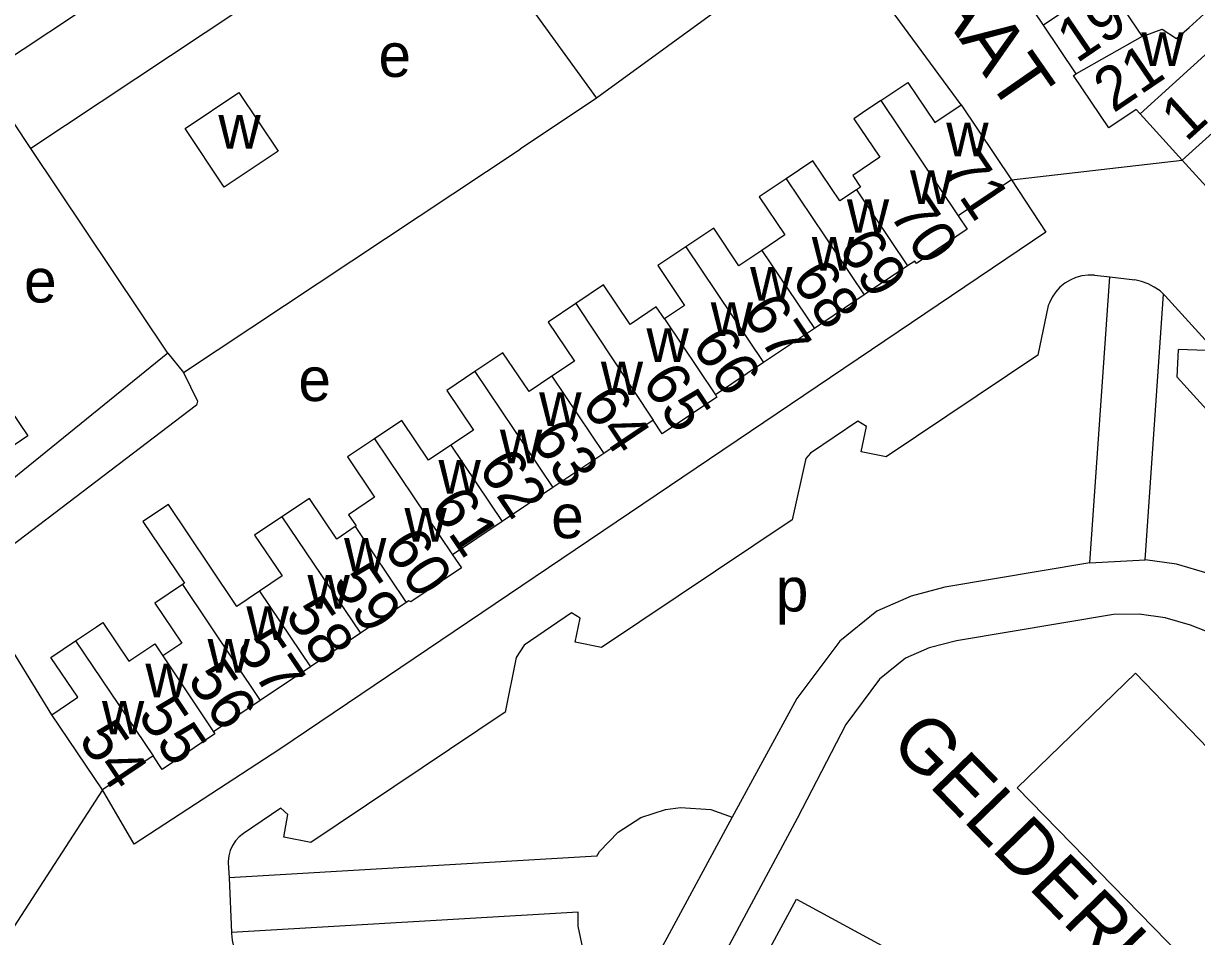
# Model space of a CAD drawing. Extents: x 158356 to 159894, y 383831 to 385260.
# Drawn here: x 158893.5 to 159000.7, y 384127.4 to 384210.9 of the extents above; entities that cross this region are included whole.
import ezdxf

# ---------------------------------------------------------------- set-up
doc = ezdxf.new("R2010")
doc.units = 0
for name, color, linetype in [('BLT_Basislijn', 7, 'Continuous'), ('BLT_Bebouwing', 7, 'Continuous'), ('BLT_Centroide', 7, 'Continuous'), ('BLT_Huisnummer', 7, 'Continuous'), ('BLT_Huisnummer_ tussenligend', 7, 'Continuous'), ('BLT_Onderverdeling_panden', 7, 'Continuous'), ('BLT_Straatnaam', 7, 'Continuous'), ('BLT_Vlakafsluiter', 7, 'Continuous')]:
    doc.layers.add(name, color=color, linetype=linetype)

msp = doc.modelspace()

# ---------------------------------------------------------------- linework, layer by layer
at = {"layer": 'BLT_Basislijn'}
for p, q in [((158930.73, 384224.98), (158945.89, 384204.06)), ((158979.18, 384203.45), (158967.44, 384219.43)), ((158961.44, 384215.4), (158945.89, 384204.06)), ((158945.89, 384204.06), (158938.9, 384199.39)), ((158906.7, 384180.74), (158894.19, 384199.45)), ((158908.13, 384178.98), (158938.9, 384199.39)), ((158990.95, 384161.58), (158992.79, 384187.71)), ((158991.37, 384187.88), (158992.79, 384187.71)), ((158992.79, 384187.71), (158995.07, 384187.44)), ((158995.99, 384161.86), (158997.69, 384186.13)), ((158987.13, 384185.1), (158986.2, 384180.57)), ((158906.7, 384180.74), (158891.84, 384168.68)), ((158906.7, 384180.74), (158908.13, 384178.98)), ((158986.2, 384180.57), (158972.33, 384171.27)), ((158990.95, 384161.58), (158995.99, 384161.86)), ((158896.12, 384147.7), (158888.48, 384160.12)), ((158964.18, 384149.17), (158958.27, 384138.32)), ((158958.27, 384138.32), (158948.85, 384120.94)), ((158912.23, 384134.16), (158912.3, 384132.79)), ((158945.92, 384134.77), (158912.3, 384132.79)), ((158912.3, 384132.79), (158912.53, 384127.8)), ((158944.2, 384129.66), (158912.53, 384127.8)), ((158912.53, 384127.8), (158912.54, 384127.69))]:
    msp.add_line(p, q, dxfattribs=at)
for points in [[(158983.8, 384196.58), (158986.94, 384191.81), (158916.93, 384144.54), (158903.63, 384135.86), (158900.74, 384140.84)], [(158991.37, 384187.88), (158990.8, 384187.89), (158990.23, 384187.81), (158989.68, 384187.66), (158989.15, 384187.43), (158988.66, 384187.13), (158988.22, 384186.77), (158987.83, 384186.35), (158987.51, 384185.88), (158987.25, 384185.36), (158987.13, 384185.1)], [(158997.69, 384186.13), (158997.36, 384186.43), (158996.83, 384186.79), (158996.27, 384187.08), (158995.68, 384187.3), (158995.07, 384187.44)], [(158997.83, 384186), (158997.69, 384186.13)], [(158997.83, 384186), (159001.78, 384181.62), (159001.54, 384181), (158999.06, 384181.08)], [(159010.91, 384165.35), (158998.93, 384178.56), (158999.06, 384181.08)], [(158908.13, 384178.98), (158909.41, 384176.35), (158909.32, 384175.99), (158888.48, 384160.12)], [(158972.33, 384171.27), (158970.07, 384171.72), (158970.54, 384174.05), (158969.76, 384174.53), (158965.43, 384171.61), (158964.99, 384171.11), (158963.74, 384165.51), (158946.33, 384153.83), (158943.94, 384154.33), (158944.39, 384156.51), (158943.59, 384157), (158939.27, 384154.07), (158938.53, 384152.92), (158937.53, 384147.93)], [(159008.97, 384156.46), (159007.32, 384157.89), (159004.61, 384159.5), (159001.77, 384160.62), (158998.86, 384161.47), (158995.99, 384161.86)], [(158990.95, 384161.58), (158977.71, 384159.35), (158974.62, 384158.54), (158971.49, 384157.17), (158968.11, 384154.43), (158964.18, 384149.17)], [(159006.64, 384151.86), (159004.38, 384153.82), (159002.4, 384155), (159000.15, 384155.88), (158997.82, 384156.56), (158995.47, 384156.88), (158993.12, 384156.87), (158978.76, 384154.46), (158976.27, 384153.81), (158974.11, 384152.86), (158971.74, 384150.94), (158968.65, 384146.8)], [(158937.53, 384147.93), (158919.78, 384136.01), (158917.31, 384136.49), (158917.67, 384138.59), (158917.02, 384139.17), (158913.62, 384136.85)], [(158968.65, 384146.8), (158964.22, 384138.2), (158955.79, 384122.55)], [(158945.92, 384134.77), (158946.16, 384135.19), (158947.84, 384136.96), (158949.94, 384138.29), (158952.17, 384139.04), (158953.56, 384139.23), (158956.33, 384139.03), (158958.27, 384138.32)], [(158913.62, 384136.85), (158913.23, 384136.53), (158912.89, 384136.16), (158912.62, 384135.74), (158912.41, 384135.28), (158912.28, 384134.79), (158912.23, 384134.29), (158912.23, 384134.16)], [(158948.85, 384120.94), (158947.78, 384121.67), (158946.44, 384123.01), (158945.35, 384124.64), (158944.62, 384126.37), (158944.21, 384128.36), (158944.2, 384129.66)], [(158912.54, 384127.69), (158912.58, 384127.1), (158912.7, 384126.52), (158912.89, 384125.96), (158913.16, 384125.44), (158913.5, 384124.95), (158913.9, 384124.52), (158914.05, 384124.38)]]:
    msp.add_lwpolyline(points, dxfattribs=at)
for points in [[(158995.11, 384151.5), (159012.51, 384133.45), (159001.73, 384123.15), (158984.32, 384141.02)], [(158964.16, 384130.84), (158973.01, 384126.02), (158969.38, 384119.33), (158960.56, 384124.2)]]:
    msp.add_lwpolyline(points, close=True, dxfattribs=at)
at = {"layer": 'BLT_Bebouwing'}
for p, q in [((158889.79, 384206.08), (158915.33, 384223.05)), ((158986.7, 384210.73), (158983.81, 384215.04)), ((158989.69, 384206.28), (158986.7, 384210.73)), ((158894.19, 384199.45), (158889.79, 384206.08)), ((158908.28, 384201.27), (158913.2, 384204.58)), ((158913.2, 384204.58), (158916.79, 384199.22)), ((158979.18, 384203.45), (158983.8, 384196.58)), ((158999.39, 384198.39), (158995.54, 384202.63)), ((158911.87, 384195.92), (158908.28, 384201.27)), ((158916.79, 384199.22), (158911.87, 384195.92)), ((158983.8, 384196.58), (158978.92, 384193.3)), ((158974.28, 384188.72), (158970.34, 384186.07)), ((158970.34, 384186.07), (158965.78, 384183.01)), ((158965.78, 384183.01), (158961.13, 384179.89)), ((158961.13, 384179.89), (158956.75, 384176.94)), ((158951.05, 384174.62), (158946.53, 384171.58)), ((158946.53, 384171.58), (158941.89, 384168.46)), ((158941.89, 384168.46), (158937.27, 384165.36)), ((158937.27, 384165.36), (158932.73, 384162.31)), ((158928.49, 384157.95), (158924.3, 384155.14)), ((158924.3, 384155.14), (158919.74, 384152.07)), ((158919.74, 384152.07), (158915.16, 384148.99)), ((158915.16, 384148.99), (158910.89, 384146.13)), ((158900.74, 384140.84), (158896.12, 384147.7)), ((158905.36, 384143.94), (158900.74, 384140.84))]:
    msp.add_line(p, q, dxfattribs=at)
for points in [[(158915.33, 384223.05), (158919.73, 384216.42), (158894.19, 384199.45)], [(158996.17, 384217.09), (158997.79, 384214.66), (158994.06, 384212.16), (158995.72, 384209.68)], [(158995.72, 384209.68), (158997.57, 384210.35), (158998.88, 384209.5), (159000.03, 384210.53), (159002.36, 384212.65), (159004.27, 384210.55)], [(158995.54, 384202.63), (158995.17, 384203.03), (158992.67, 384201.35), (158989.46, 384206.13), (158989.69, 384206.28)], [(158971.85, 384203.83), (158974.32, 384205.48), (158976.78, 384201.83), (158979.18, 384203.45)], [(158971.85, 384203.83), (158970.17, 384202.7), (158969.39, 384202.17), (158971.75, 384198.65), (158969.28, 384196.99), (158970, 384195.92), (158969.62, 384195.67)], [(158969.62, 384195.67), (158968.12, 384194.66), (158965.65, 384198.33), (158963.2, 384196.68)], [(159003.21, 384194.18), (159000, 384197.72), (158999.39, 384198.39)], [(158963.2, 384196.68), (158960.75, 384195.04), (158963.09, 384191.55), (158960.99, 384190.14)], [(158978.92, 384193.3), (158979.75, 384192.07), (158975.11, 384188.94), (158974.95, 384189.17), (158974.28, 384188.72)], [(158960.99, 384190.14), (158958.89, 384188.73), (158956.58, 384192.17), (158954.03, 384190.46)], [(158954.03, 384190.46), (158951.48, 384188.75), (158953.92, 384185.11), (158952.09, 384183.88)], [(158952.09, 384183.88), (158951.34, 384184.98), (158948.94, 384183.37), (158946.52, 384186.98), (158944, 384185.28)], [(158944, 384185.28), (158941.47, 384183.58), (158943.86, 384180.03), (158941.79, 384178.64)], [(158941.79, 384178.64), (158939.71, 384177.24), (158937.33, 384180.78), (158934.77, 384179.06)], [(158934.77, 384179.06), (158932.2, 384177.33), (158934.63, 384173.72), (158932.58, 384172.34)], [(158956.75, 384176.94), (158956.87, 384176.73), (158951.88, 384173.38), (158951.05, 384174.62)], [(158892.35, 384175.53), (158893.93, 384173.18), (158890.41, 384170.81), (158891.84, 384168.68)], [(158932.58, 384172.34), (158930.52, 384170.96), (158928.08, 384174.59), (158925.6, 384172.92)], [(158925.6, 384172.92), (158923.12, 384171.26), (158925.6, 384167.57), (158923.23, 384165.98), (158923.92, 384164.95), (158923.83, 384164.89)], [(158923.83, 384164.89), (158922.14, 384163.75), (158919.64, 384167.47), (158917.14, 384165.79)], [(158915.09, 384158.99), (158913.02, 384157.6), (158910.55, 384161.27), (158906.78, 384166.9), (158904.43, 384165.36), (158908.23, 384159.71), (158908.04, 384159.59)], [(158917.14, 384165.79), (158914.64, 384164.11), (158917.15, 384160.38), (158915.09, 384158.99)], [(158932.73, 384162.31), (158933.54, 384161.11), (158928.92, 384158.01), (158928.72, 384158.11), (158928.49, 384157.95)], [(158908.04, 384159.59), (158905.53, 384157.9), (158907.98, 384154.25), (158906.24, 384153.08)], [(158898.29, 384154.46), (158900.18, 384155.73), (158900.78, 384156.13), (158903.15, 384152.59), (158905.51, 384154.17), (158906.24, 384153.08)], [(158896.12, 384147.7), (158898.48, 384149.29), (158896.03, 384152.94), (158898.29, 384154.46)], [(158910.89, 384146.13), (158911.02, 384145.94), (158906.2, 384142.7), (158905.36, 384143.94)]]:
    msp.add_lwpolyline(points, dxfattribs=at)
at = {"layer": 'BLT_Onderverdeling_panden'}
for p, q in [((158996.17, 384217.09), (158986.7, 384210.73)), ((159004.27, 384210.55), (158995.54, 384202.63)), ((158995.72, 384209.68), (158989.69, 384206.28)), ((158971.85, 384203.83), (158978.92, 384193.3)), ((159005.05, 384203.53), (158999.39, 384198.39)), ((158963.2, 384196.68), (158970.34, 384186.07)), ((158969.62, 384195.67), (158974.28, 384188.72)), ((158954.03, 384190.46), (158961.13, 384179.89)), ((158960.99, 384190.14), (158965.78, 384183.01)), ((158944, 384185.28), (158951.05, 384174.62)), ((158952.09, 384183.88), (158956.75, 384176.94)), ((158934.77, 384179.06), (158941.89, 384168.46)), ((158941.79, 384178.64), (158946.53, 384171.58)), ((158925.6, 384172.92), (158932.73, 384162.31)), ((158932.58, 384172.34), (158937.27, 384165.36)), ((158917.14, 384165.79), (158924.3, 384155.14)), ((158923.83, 384164.89), (158928.49, 384157.95)), ((158908.04, 384159.59), (158915.16, 384148.99)), ((158915.09, 384158.99), (158919.74, 384152.07)), ((158898.29, 384154.46), (158905.36, 384143.94)), ((158906.24, 384153.08), (158910.89, 384146.13))]:
    msp.add_line(p, q, dxfattribs=at)
at = {"layer": 'BLT_Vlakafsluiter'}
for p, q in [((158983.8, 384196.58), (158999.39, 384198.39)), ((158900.74, 384140.84), (158892.63, 384128.3))]:
    msp.add_line(p, q, dxfattribs=at)

# ---------------------------------------------------------------- texts
at = {"layer": 'BLT_Centroide'}
for s, p in [('w', (158995.66, 384207)), ('e', (158925.96, 384206)), ('w', (158911.33, 384199.44)), ('w', (158977.83, 384198.73)), ('w', (158974.52, 384194.38)), ('w', (158968.75, 384191.75)), ('w', (158965.55, 384188.28)), ('e', (158893.58, 384185.38)), ('w', (158959.91, 384185.56)), ('w', (158956.31, 384182.33)), ('w', (158950.44, 384179.95)), ('w', (158946.27, 384176.91)), ('e', (158918.64, 384176.37)), ('w', (158940.64, 384174.09)), ('w', (158937.05, 384170.67)), ('w', (158931.44, 384167.91)), ('w', (158928.33, 384163.53)), ('e', (158941.74, 384163.83)), ('w', (158922.81, 384160.78)), ('w', (158919.47, 384157.39)), ('p', (158962.26, 384157.14)), ('w', (158913.89, 384154.53)), ('w', (158910.34, 384151.55)), ('w', (158904.66, 384149.3)), ('w', (158900.69, 384145.89))]:
    msp.add_text(s, height=4, dxfattribs=at).set_placement(p)
at = {"layer": 'BLT_Huisnummer'}
for s, rotation, p in [('21', 34.1084, (158993.1, 384202.65)), ('1', 42.1914, (158999.74, 384199.98)), ('71', 303.8915, (158977.25, 384197.55)), ('68', 303.8915, (158963.58, 384187.55)), ('66', 303.8915, (158954.48, 384181.47)), ('64', 303.8915, (158944.4, 384176.13)), ('62', 303.8915, (158934.97, 384170.27)), ('60', 303.8915, (158926.3, 384163.04)), ('58', 303.8915, (158917.34, 384156.84)), ('56', 303.8915, (158908.41, 384150.91)), ('54', 303.8915, (158898.47, 384145.45))]:
    msp.add_text(s, height=4, rotation=rotation, dxfattribs=at).set_placement(p)
at = {"layer": 'BLT_Huisnummer_ tussenligend'}
for s, rotation, p in [('19', 34.1084, (158989.75, 384207.19)), ('70', 303.8915, (158972.53, 384193.48)), ('69', 303.8915, (158967.85, 384190.41)), ('67', 303.8915, (158959.07, 384184.46)), ('65', 303.8915, (158949.93, 384178.12)), ('63', 303.8915, (158939.71, 384172.99)), ('61', 303.8915, (158930.58, 384166.77)), ('59', 303.8915, (158921.67, 384159.79)), ('57', 303.8915, (158912.84, 384153.87)), ('55', 303.8915, (158903.88, 384147.66))]:
    msp.add_text(s, height=4, rotation=rotation, dxfattribs=at).set_placement(p)
at = {"layer": 'BLT_Straatnaam'}
for s, rotation, p in [('WINTERSWIJKSTRAAT', 304.7971, (158942.06, 384262.55)), ('GELDERLANDPLEIN', 314.1951, (158972.54, 384144.95))]:
    msp.add_text(s, height=5, rotation=rotation, dxfattribs=at).set_placement(p)

doc.saveas('drawing.dxf')
